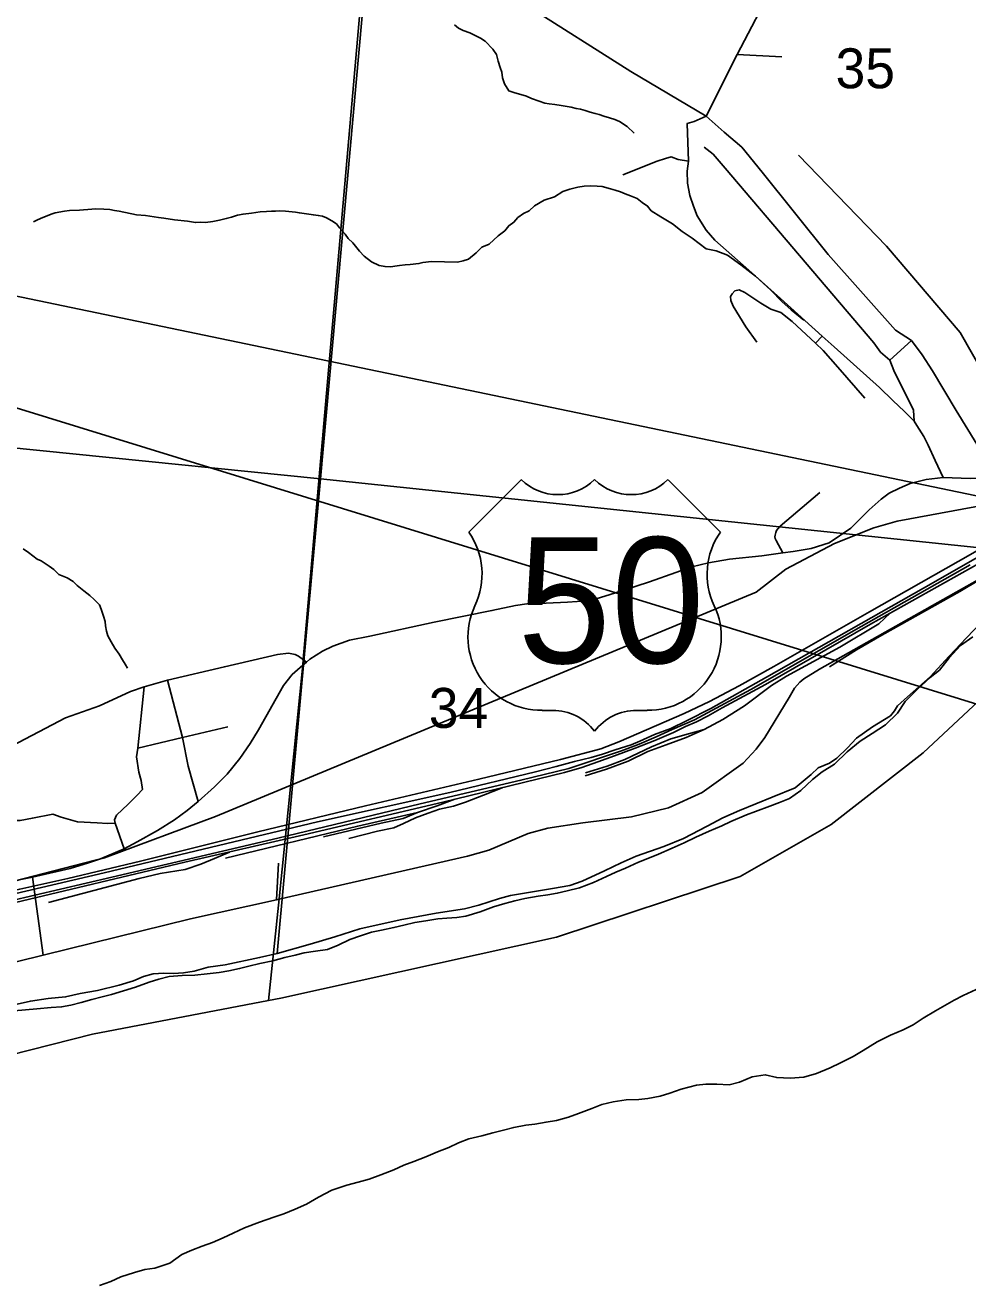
# Model space of a CAD drawing. Extents: x 0 to 34, y -2 to 22.
# Drawn here: x 6.75 to 7.738, y 14.734 to 16.052 of the extents above; entities that cross this region are included whole.
import ezdxf

# ---------------------------------------------------------------- set-up
doc = ezdxf.new("R2010")
doc.units = 0
for name, color, linetype in [('GM_X_City_Street', 7, 'Continuous'), ('GM_X_County_Road', 7, 'Continuous'), ('GM_X_Major_River', 7, 'Continuous'), ('GM_X_Minor_River', 7, 'Continuous'), ('GM_X_Rail_Line', 7, 'Continuous'), ('GM_X_Section', 7, 'Continuous'), ('GM_X_Section_Text', 7, 'Continuous'), ('GM_X_US_Location', 7, 'Continuous'), ('GM_X_US_Route', 7, 'Continuous'), ('GM_X_US_Shield', 7, 'Continuous'), ('SH_Cut_Line', 7, 'Continuous'), ('SH_Data', 7, 'Continuous')]:
    doc.layers.add(name, color=color, linetype=linetype)

msp = doc.modelspace()

# ---------------------------------------------------------------- linework, layer by layer
at = {"layer": 'GM_X_City_Street'}
for p, q in [((7.4964, 16.0209), (7.5431, 16.0184)), ((7.5783, 15.7185), (7.5854, 15.7256)), ((7.6564, 15.7004), (7.6791, 15.7211)), ((7.0137, 15.135), (7.0157, 15.1732)), ((6.7691, 15.077), (6.758, 15.1588))]:
    msp.add_line(p, q, dxfattribs=at)
for points in [[(7.7121, 15.5775), (7.7036, 15.5952), (7.6965, 15.6115), (7.6919, 15.6206), (7.6845, 15.6322), (7.6819, 15.6365), (7.6718, 15.6467), (7.6595, 15.6584), (7.6454, 15.6717), (7.598, 15.7144), (7.5854, 15.7256), (7.5416, 15.765), (7.5084, 15.795), (7.4849, 15.8157), (7.4729, 15.8264), (7.4639, 15.8367), (7.4545, 15.8517), (7.4506, 15.8619), (7.4465, 15.8732), (7.4442, 15.886), (7.444, 15.8987), (7.4453, 15.909), (7.444, 15.9487), (7.4511, 15.9506), (7.4637, 15.9561)], [(7.4453, 15.909), (7.4346, 15.911), (7.4271, 15.9136), (7.4211, 15.912), (7.4123, 15.909), (7.3764, 15.8947)], [(7.6819, 15.6365), (7.6809, 15.648), (7.6603, 15.6898), (7.6564, 15.7004), (7.6466, 15.709), (7.6396, 15.7188), (7.4836, 15.9018), (7.4711, 15.9164), (7.4617, 15.9238)], [(7.82, 15.5775), (7.7958, 15.6223), (7.7543, 15.6867), (7.7301, 15.7295), (7.6526, 15.82), (7.5606, 15.9153)], [(7.6299, 15.6608), (7.6018, 15.6932), (7.5865, 15.7105), (7.5783, 15.7185), (7.554, 15.7412), (7.542, 15.7504), (7.5314, 15.7539), (7.5211, 15.7603), (7.5116, 15.7665), (7.5043, 15.7716), (7.4984, 15.7742), (7.494, 15.7731), (7.491, 15.77), (7.4894, 15.7672), (7.4897, 15.7631), (7.492, 15.7572)], [(7.5168, 15.7193), (7.5053, 15.7353), (7.492, 15.7572)], [(7.5442, 15.4986), (7.537, 15.5114), (7.5361, 15.5136), (7.5359, 15.5153), (7.5361, 15.5172), (7.5367, 15.52), (7.5376, 15.5221), (7.5389, 15.5239), (7.5415, 15.5267), (7.5828, 15.5617)], [(6.6909, 15.0578), (6.7691, 15.077), (6.9235, 15.1148), (7.0137, 15.135), (7.0164, 15.1356), (7.2137, 15.1806), (7.2359, 15.1871), (7.2771, 15.2043), (7.2978, 15.2101), (7.3344, 15.2157), (7.3854, 15.2219), (7.4244, 15.2312), (7.4595, 15.2475), (7.5026, 15.2783), (7.5163, 15.2928), (7.5251, 15.3049), (7.5507, 15.3471), (7.5564, 15.3566), (7.5618, 15.363), (7.5662, 15.3665), (7.5825, 15.3766), (7.8057, 15.5024)], [(6.7293, 15.2925), (6.7926, 15.3256), (6.8279, 15.3381), (6.8606, 15.3531), (6.8747, 15.3582), (6.8994, 15.365), (6.959, 15.3792), (7.0147, 15.392), (7.0262, 15.3933), (7.0332, 15.3919), (7.0367, 15.3903), (7.0418, 15.3864), (7.0448, 15.3839)], [(6.9315, 15.2379), (6.9211, 15.2749), (6.9152, 15.3051), (6.8994, 15.365)], [(6.8539, 15.1885), (6.8444, 15.2153), (6.8438, 15.2188), (6.846, 15.2235), (6.858, 15.2352), (6.8676, 15.2445), (6.8732, 15.2507), (6.8716, 15.26), (6.8694, 15.2686), (6.867, 15.2846), (6.8681, 15.294), (6.8747, 15.3582)], [(6.8681, 15.294), (6.9152, 15.3051), (6.9627, 15.3161)], [(6.6575, 15.1353), (6.6562, 15.1406), (6.6549, 15.1485), (6.6549, 15.1562), (6.6558, 15.1616), (6.661, 15.1682), (6.6808, 15.1838), (6.6889, 15.1904), (6.6944, 15.1967), (6.6977, 15.2048), (6.7006, 15.2098), (6.7123, 15.2165), (6.7244, 15.2182), (6.7448, 15.218), (6.7577, 15.2205), (6.7792, 15.2245), (6.7878, 15.2216), (6.8049, 15.2168), (6.8257, 15.2155), (6.8365, 15.2148), (6.8444, 15.2153)]]:
    msp.add_lwpolyline(points, dxfattribs=at)
at = {"layer": 'GM_X_County_Road'}
for points in [[(7.4637, 15.9561), (7.4964, 16.0209), (7.5352, 16.0954), (7.5404, 16.1047), (7.558, 16.1266), (7.6348, 16.2084), (7.6443, 16.2237), (7.6522, 16.2368), (7.6565, 16.247), (7.6579, 16.2514), (7.6603, 16.2699), (7.6794, 16.4469), (7.6823, 16.4535), (7.6835, 16.4563), (7.6891, 16.469), (7.7056, 16.5046), (7.7084, 16.5106), (7.7098, 16.5193), (7.7437, 16.7928), (7.7563, 16.8973), (7.7576, 16.9073)], [(7.112, 16.1885), (7.1743, 16.1656), (7.1952, 16.1517), (7.2074, 16.1396), (7.2198, 16.1237), (7.2337, 16.1048), (7.2425, 16.0951), (7.2522, 16.0876), (7.2734, 16.0738), (7.3847, 16.003), (7.4637, 15.9561)], [(7.4637, 15.9561), (7.4828, 15.9396), (7.501, 15.9238), (7.5226, 15.8975), (7.5916, 15.8113), (7.6622, 15.7321), (7.6791, 15.7211), (7.69, 15.7062), (7.7008, 15.6892), (7.7259, 15.6477), (7.769, 15.5773)]]:
    msp.add_lwpolyline(points, dxfattribs=at)
at = {"layer": 'GM_X_Major_River'}
for points in [[(7.7432, 15.4105), (7.7304, 15.4014), (7.7183, 15.3884), (7.7082, 15.3757), (7.6985, 15.368), (7.6853, 15.3558), (7.6724, 15.3429), (7.6642, 15.3305), (7.6517, 15.3183), (7.6378, 15.3092), (7.6251, 15.3012), (7.6116, 15.2901), (7.5983, 15.2772), (7.5852, 15.2692), (7.5752, 15.2611), (7.5631, 15.2496), (7.5512, 15.2412), (7.5408, 15.2369), (7.5305, 15.233), (7.5155, 15.2276), (7.506, 15.2241), (7.4898, 15.2169), (7.4803, 15.2126), (7.4668, 15.2069), (7.453, 15.2004), (7.4407, 15.1946), (7.4281, 15.1889), (7.4139, 15.1828), (7.4043, 15.1788), (7.3928, 15.1742), (7.3794, 15.1681), (7.369, 15.1638), (7.3594, 15.1595), (7.3456, 15.153), (7.331, 15.1476), (7.3181, 15.1442), (7.3078, 15.1418), (7.2978, 15.1401), (7.2879, 15.1389), (7.2738, 15.1362), (7.2632, 15.1338), (7.2528, 15.131), (7.241, 15.1275), (7.2268, 15.1222), (7.2119, 15.1176), (7.2024, 15.1163), (7.1921, 15.1155), (7.1826, 15.1149), (7.1701, 15.113), (7.1586, 15.111), (7.1468, 15.1082), (7.1365, 15.1058), (7.1235, 15.1031), (7.1132, 15.1011), (7.1014, 15.0972), (7.0903, 15.0933), (7.078, 15.0872), (7.0669, 15.0829), (7.0543, 15.081), (7.0425, 15.0794), (7.033, 15.0769), (7.0223, 15.0746), (7.0097, 15.0711), (6.9959, 15.068), (6.9845, 15.0653), (6.9749, 15.0628), (6.9635, 15.0605), (6.9536, 15.0588), (6.941, 15.0572), (6.9281, 15.0561), (6.9148, 15.0556), (6.9011, 15.0545), (6.8904, 15.0517), (6.8801, 15.0485), (6.8659, 15.0432), (6.8407, 15.0355)], [(6.8407, 15.0355), (6.8308, 15.0331), (6.8201, 15.0303), (6.809, 15.0272), (6.7979, 15.0244), (6.7884, 15.0227), (6.7774, 15.0219), (6.7625, 15.0207), (6.7504, 15.0195), (6.7386, 15.0187)], [(6.8282, 14.7307), (6.84, 14.735), (6.8504, 14.7397), (6.8649, 14.7442), (6.8756, 14.7474), (6.8859, 14.749), (6.9016, 14.7539), (6.9144, 14.7631), (6.9247, 14.7678), (6.9358, 14.772), (6.9465, 14.7756), (6.9577, 14.7806), (6.968, 14.7856), (6.9799, 14.791), (6.9956, 14.7971), (7.0109, 14.8024), (7.0213, 14.8059), (7.0332, 14.8106), (7.0451, 14.816), (7.0574, 14.8232), (7.0716, 14.8305), (7.0873, 14.8358), (7.0991, 14.8389), (7.1106, 14.842), (7.1228, 14.8466), (7.1366, 14.852), (7.147, 14.8567), (7.1573, 14.8606), (7.17, 14.8656), (7.1822, 14.8706), (7.1941, 14.8752), (7.2041, 14.8803), (7.2152, 14.8845), (7.2286, 14.8876), (7.2404, 14.8907), (7.2515, 14.8935), (7.2622, 14.8963), (7.2748, 14.8986), (7.2843, 14.8999), (7.2961, 14.9019), (7.3071, 14.9035), (7.3194, 14.907), (7.3301, 14.9109), (7.3439, 14.9162), (7.3546, 14.9205), (7.3664, 14.9232), (7.3798, 14.9252), (7.3931, 14.9256), (7.4026, 14.9265), (7.4155, 14.9292), (7.4258, 14.9324), (7.4377, 14.9366), (7.4538, 14.9408), (7.4636, 14.9417), (7.475, 14.9418), (7.4879, 14.9411), (7.4986, 14.9438), (7.512, 14.9492), (7.5257, 14.9515), (7.5378, 14.9485), (7.5518, 14.9478), (7.5663, 14.949), (7.5793, 14.9528), (7.5938, 14.9589), (7.6046, 14.9639), (7.618, 14.9708), (7.6284, 14.977), (7.6431, 14.9861), (7.6569, 14.993), (7.6703, 14.9987), (7.6807, 15.0038), (7.6911, 15.0107), (7.7042, 15.0184), (7.7138, 15.0242), (7.7235, 15.0296), (7.7331, 15.0347), (7.7469, 15.0408)]]:
    msp.add_lwpolyline(points, dxfattribs=at)
at = {"layer": 'GM_X_Minor_River'}
for points in [[(7.3885, 15.9383), (7.3811, 15.9454), (7.3729, 15.9505), (7.368, 15.9526), (7.3624, 15.9546), (7.3567, 15.9563), (7.3518, 15.958), (7.3473, 15.9589), (7.3424, 15.9605), (7.3371, 15.9622), (7.3322, 15.9635), (7.3276, 15.9644), (7.3223, 15.9657), (7.3117, 15.9675), (7.3053, 15.9684), (7.2992, 15.9693), (7.2947, 15.9699), (7.2887, 15.9719), (7.2808, 15.9748), (7.2755, 15.9772), (7.2623, 15.981), (7.257, 15.9827), (7.2523, 15.9901), (7.2502, 15.9966), (7.2496, 16.0023), (7.2478, 16.0073), (7.2457, 16.0139), (7.244, 16.0208), (7.2403, 16.0266), (7.2322, 16.0348), (7.2273, 16.038), (7.2224, 16.0404), (7.2161, 16.0436), (7.2093, 16.0461), (7.2044, 16.0485), (7.1999, 16.0521)], [(7.4061, 15.8571), (7.4024, 15.8621), (7.3968, 15.8657), (7.3916, 15.87), (7.3845, 15.8729), (7.3788, 15.875), (7.3739, 15.877), (7.3683, 15.8787), (7.3634, 15.88), (7.3547, 15.8825), (7.3494, 15.883), (7.3425, 15.8832), (7.3361, 15.883), (7.3292, 15.8817), (7.3208, 15.8796), (7.3135, 15.8772), (7.305, 15.8717), (7.2942, 15.8682), (7.2838, 15.8624), (7.2783, 15.8572), (7.2722, 15.8543), (7.2663, 15.8499), (7.2624, 15.8451), (7.257, 15.8414), (7.2527, 15.8362), (7.2457, 15.8307), (7.2363, 15.8222), (7.2286, 15.819), (7.2228, 15.813), (7.2146, 15.8064), (7.2092, 15.8047), (7.2031, 15.8033), (7.1761, 15.8041), (7.167, 15.8028), (7.1627, 15.8018), (7.1536, 15.8009), (7.1483, 15.8003), (7.1425, 15.7997), (7.1376, 15.799), (7.1334, 15.7984), (7.1273, 15.7986), (7.1212, 15.7999), (7.113, 15.8035), (7.1055, 15.8095), (7.1004, 15.8149), (7.0934, 15.8235), (7.0885, 15.8282), (7.0856, 15.8325), (7.0797, 15.8391), (7.0764, 15.8434), (7.0715, 15.8466), (7.0659, 15.8498), (7.0618, 15.8514), (7.0573, 15.8523), (7.0523, 15.8528), (7.0474, 15.8537), (7.0425, 15.8542), (7.0375, 15.8548), (7.0334, 15.8556), (7.0228, 15.8567), (7.0167, 15.8569), (7.0125, 15.8566), (7.0083, 15.8567), (7.003, 15.8565), (6.9965, 15.8559), (6.9873, 15.8546), (6.9786, 15.8537), (6.9725, 15.8524), (6.9663, 15.8503), (6.9609, 15.8489), (6.9537, 15.8472), (6.9468, 15.8459), (6.9392, 15.8449), (6.9338, 15.8451), (6.9285, 15.8448), (6.9202, 15.8462), (6.9065, 15.8477), (6.8955, 15.8492), (6.8899, 15.8501), (6.8762, 15.852), (6.8667, 15.853), (6.8486, 15.8566), (6.8437, 15.8575), (6.8388, 15.8584), (6.8327, 15.8589), (6.8243, 15.8592), (6.8201, 15.8589), (6.8072, 15.8577), (6.7965, 15.8573), (6.7915, 15.8567), (6.7816, 15.855), (6.7774, 15.8536), (6.7732, 15.8518), (6.7686, 15.8501), (6.7632, 15.8475), (6.7589, 15.8454)], [(7.4061, 15.8571), (7.4163, 15.8508), (7.4286, 15.8433), (7.4387, 15.8355), (7.4492, 15.8285), (7.4637, 15.8171), (7.4743, 15.815), (7.4863, 15.8106), (7.5001, 15.8004), (7.5154, 15.7887), (7.5314, 15.7739), (7.5432, 15.7619), (7.5529, 15.7533), (7.5663, 15.7424)], [(6.7481, 15.5029), (6.7537, 15.499), (6.7627, 15.4919), (6.7668, 15.4902), (6.7754, 15.4847), (6.7802, 15.4811), (6.7854, 15.476), (6.7941, 15.4723), (6.8004, 15.4684), (6.8045, 15.4644), (6.8116, 15.4589), (6.8179, 15.4538), (6.8223, 15.4495), (6.8279, 15.444), (6.8297, 15.4397), (6.8321, 15.4321), (6.8339, 15.4267), (6.8342, 15.4221), (6.8355, 15.4164), (6.8369, 15.4117), (6.8402, 15.4052), (6.8442, 15.3986), (6.8486, 15.3924), (6.8522, 15.3866), (6.8551, 15.3819), (6.8573, 15.3777)]]:
    msp.add_lwpolyline(points, dxfattribs=at)
at = {"layer": 'GM_X_Rail_Line'}
for points in [[(7.3254, 18.3889), (7.2924, 18.0527), (7.2805, 17.9249), (7.2705, 17.818), (7.2479, 17.5755), (7.2301, 17.3765), (7.2142, 17.2276), (7.2013, 17.0768), (7.1819, 16.9294), (7.1729, 16.8603), (7.1419, 16.5212), (7.1299, 16.384), (7.1117, 16.189), (7.0415, 15.3869), (7.041, 15.3813), (7.0162, 15.1361), (7.0052, 15.0295), (7.018, 15.0319), (7.3068, 15.0956), (7.4995, 15.1593), (7.5948, 15.214), (7.6912, 15.289), (7.9856, 15.5639)], [(3.2132, 16.1958), (3.4289, 16.0129), (3.5157, 15.9354), (3.8272, 15.5543), (4.0672, 15.2682), (4.251, 15.1231), (4.3199, 15.0739), (4.5092, 14.9662), (4.7242, 14.8927), (4.942, 14.8608), (5.225, 14.8332), (5.6876, 14.8174), (5.8521, 14.8361), (5.9916, 14.8618), (6.1483, 14.9087), (6.6423, 15.1295), (6.8334, 15.1788), (6.9496, 15.2223), (7.5162, 15.4575), (7.5472, 15.4815), (7.5981, 15.5082), (7.6394, 15.5247), (7.6638, 15.5316), (7.8133, 15.5592)], [(6.0485, 14.702), (6.1464, 14.7771), (6.2416, 14.8366), (6.3391, 14.8719), (6.8207, 14.994), (7.0052, 15.0295), (7.0162, 15.1361), (7.041, 15.3813), (7.0415, 15.3869), (7.1117, 16.189)], [(6.6146, 15.1059), (6.6312, 15.1147), (6.6662, 15.1263), (6.7028, 15.1364), (6.7444, 15.1462), (6.795, 15.1573), (6.871, 15.1755), (6.994, 15.2061), (7.1067, 15.2333), (7.2257, 15.2613), (7.311, 15.282), (7.3534, 15.293), (7.3722, 15.3005), (7.4409, 15.3303), (7.4674, 15.3427), (7.4983, 15.3593), (7.5346, 15.3794), (7.6351, 15.4369), (7.7278, 15.4896), (7.8167, 15.5401), (7.8706, 15.57), (7.8897, 15.5778), (7.9146, 15.5882)], [(6.833, 15.1632), (7.0564, 15.2165), (7.1953, 15.2475), (7.2848, 15.2692), (7.3066, 15.2746), (7.3257, 15.28), (7.3433, 15.2839), (7.3552, 15.2874), (7.3684, 15.2921), (7.3853, 15.2972), (7.3942, 15.3012), (7.4097, 15.3082), (7.4267, 15.3146), (7.4438, 15.3227), (7.4688, 15.3355), (7.5269, 15.3683), (7.702, 15.4676), (7.8432, 15.5481), (7.9089, 15.585), (7.9146, 15.5882)], [(7.5931, 15.3792), (7.6214, 15.397), (7.6477, 15.4122), (7.7296, 15.4582), (7.7514, 15.4709), (7.7645, 15.4821), (7.7706, 15.4909), (7.777, 15.4998), (7.7912, 15.511)], [(6.7327, 15.1303), (6.9174, 15.1742), (7.0421, 15.2029), (7.1879, 15.2374), (7.3155, 15.2682), (7.3336, 15.2737), (7.3504, 15.2795), (7.3677, 15.2858), (7.3894, 15.2938), (7.41, 15.302), (7.4294, 15.3103), (7.4422, 15.3165), (7.4535, 15.3215), (7.466, 15.3277), (7.4807, 15.3361), (7.5258, 15.3607), (7.636, 15.4237), (7.7757, 15.5021)], [(7.7403, 15.4861), (7.6263, 15.4214), (7.5105, 15.3554), (7.4515, 15.3235), (7.428, 15.3133), (7.4114, 15.3056), (7.3935, 15.2981), (7.3751, 15.2911), (7.3199, 15.2725), (7.2697, 15.2603), (7.1642, 15.2356), (7.0148, 15.1995), (6.8409, 15.1586), (6.7334, 15.1336)], [(7.4617, 15.3133), (7.4814, 15.324), (7.5038, 15.3381), (7.5322, 15.3595), (7.548, 15.3692), (7.6037, 15.3996), (7.6449, 15.424), (7.6567, 15.4353)], [(7.3369, 15.2649), (7.3592, 15.2717), (7.3821, 15.2803), (7.4027, 15.2902), (7.422, 15.2972), (7.443, 15.3049), (7.4617, 15.3133)], [(7.3373, 15.268), (7.36, 15.2749), (7.3784, 15.2819), (7.4065, 15.2953), (7.4266, 15.3036), (7.4453, 15.3088), (7.4617, 15.3133)], [(7.2501, 15.2524), (7.2306, 15.2445), (7.2116, 15.2373), (7.1989, 15.2331), (7.1844, 15.2298), (7.1725, 15.2256), (7.1592, 15.2209), (7.1466, 15.2148), (7.1364, 15.2104), (7.1195, 15.2069), (7.0892, 15.1991)], [(7.2003, 15.2404), (7.1818, 15.2335), (7.1612, 15.2263)], [(7.1612, 15.2263), (7.0986, 15.2121), (6.96, 15.1787)], [(7.1612, 15.2263), (7.1461, 15.2202), (7.1233, 15.2153), (7.0628, 15.2009)], [(6.7746, 15.1322), (6.8695, 15.1571), (6.8917, 15.1624), (6.918, 15.1668), (6.9343, 15.1723), (6.9486, 15.1782), (6.9643, 15.185)], [(5.906, 14.8342), (5.9354, 14.8392), (5.9688, 14.8461), (6.0064, 14.8549), (6.0302, 14.8613), (6.0619, 14.8708), (6.0856, 14.8783), (6.1062, 14.8854), (6.1226, 14.8912), (6.1385, 14.8972), (6.1578, 14.9048), (6.1797, 14.914), (6.2093, 14.927), (6.2632, 14.9508), (6.3927, 15.0082), (6.5799, 15.0916), (6.605, 15.1021), (6.6251, 15.11), (6.642, 15.1158), (6.6615, 15.1219), (6.6847, 15.1285), (6.833, 15.1632)]]:
    msp.add_lwpolyline(points, dxfattribs=at)
at = {"layer": 'GM_X_Section'}
for points in [[(7.1499, 16.5781), (7.0595, 15.5763), (6.0281, 15.6802), (6.1288, 16.703)], [(8.1243, 16.4653), (8.036, 15.6699), (8.0185, 15.6495), (8.0091, 15.6379), (8.0044, 15.6324), (7.9936, 15.622), (7.9816, 15.6105), (7.958, 15.591), (7.9342, 15.576), (7.9154, 15.5647), (7.9046, 15.5577), (7.8981, 15.5526), (7.864, 15.5196), (7.8404, 15.4978), (7.8376, 15.4949), (7.0595, 15.5763), (7.1499, 16.5781)]]:
    msp.add_lwpolyline(points, close=True, dxfattribs=at)
for points in [[(6.0281, 15.6802), (7.0595, 15.5763), (7.0141, 15.0788), (6.9958, 15.0743), (6.9596, 15.0668), (6.9418, 15.0642), (6.9273, 15.06), (6.9162, 15.0584), (6.9056, 15.0578), (6.8954, 15.0581), (6.8844, 15.0572), (6.8741, 15.0544), (6.8638, 15.0501), (6.8485, 15.0455), (6.826, 15.04), (6.8078, 15.0366), (6.7925, 15.0331), (6.7743, 15.0313), (6.7557, 15.0287), (6.7386, 15.0249)], [(7.7535, 15.4271), (7.7361, 15.4093), (7.7186, 15.3904), (7.6984, 15.3685), (7.6748, 15.3475), (7.6644, 15.3382), (7.6612, 15.333), (7.6569, 15.3278), (7.6381, 15.3161), (7.6212, 15.3044), (7.6118, 15.2943), (7.6006, 15.2832), (7.5929, 15.2781), (7.581, 15.2731), (7.5737, 15.2661), (7.5571, 15.2524), (7.533, 15.2424), (7.4986, 15.2284), (7.4814, 15.2208), (7.4649, 15.2121), (7.4399, 15.199), (7.4193, 15.1908), (7.3903, 15.1808), (7.3746, 15.1736), (7.3574, 15.1653), (7.334, 15.1545), (7.321, 15.1499), (7.3028, 15.1469), (7.2586, 15.1395), (7.2472, 15.1364), (7.2255, 15.1293), (7.2106, 15.1255), (7.1809, 15.1209), (7.1433, 15.1138), (7.101, 15.1045), (7.0747, 15.096), (7.0487, 15.0883), (7.0141, 15.0788), (7.0595, 15.5763), (7.8376, 15.4949)]]:
    msp.add_lwpolyline(points, dxfattribs=at)
at = {"layer": 'GM_X_US_Route'}
for points in [[(7.5442, 15.4986), (7.5549, 15.4999), (7.5739, 15.5031), (7.5927, 15.5089), (7.6154, 15.5243), (7.6345, 15.5437), (7.6471, 15.5548), (7.6554, 15.5611), (7.6663, 15.5665), (7.6776, 15.5711), (7.6945, 15.5753), (7.7121, 15.5775), (7.7405, 15.5764), (7.769, 15.5773), (7.8026, 15.577), (7.82, 15.5775), (7.8365, 15.5784), (7.8458, 15.5805)], [(7.0448, 15.3839), (7.0484, 15.3871), (7.0618, 15.3956), (7.0725, 15.4009), (7.0899, 15.4071), (7.1113, 15.4114), (7.1787, 15.4258), (7.2393, 15.438), (7.264, 15.4435), (7.2758, 15.445), (7.296, 15.4459), (7.3186, 15.4469), (7.3387, 15.4483), (7.3494, 15.4506), (7.3623, 15.4545), (7.3776, 15.4594), (7.4043, 15.4681), (7.4321, 15.4779), (7.4489, 15.4838), (7.4661, 15.4881), (7.4884, 15.4918), (7.5222, 15.4955), (7.5442, 15.4986)], [(6.8165, 15.1738), (6.829, 15.1779), (6.8539, 15.1885), (6.8675, 15.1956), (6.889, 15.2075), (6.9068, 15.2189), (6.9198, 15.2286), (6.9315, 15.2379), (6.9486, 15.2532), (6.9618, 15.2667), (6.9752, 15.2831), (6.986, 15.2988), (6.9946, 15.313), (7.0208, 15.3594), (7.03, 15.371), (7.0412, 15.3807), (7.0448, 15.3839)], [(6.7178, 15.1504), (6.7319, 15.1533), (6.758, 15.1588), (6.7972, 15.1676), (6.8165, 15.1738)]]:
    msp.add_lwpolyline(points, dxfattribs=at)
at = {"layer": 'GM_X_US_Shield'}
for p, q in [((7.27, 15.5752), (7.215, 15.5203)), ((7.4787, 15.5203), (7.4238, 15.5752)), ((7.2919, 15.3335), (7.3029, 15.3335)), ((7.3908, 15.3335), (7.4018, 15.3335))]:
    msp.add_line(p, q, dxfattribs=at)
for centre, radius, start, end in [((7.3084, 15.6145), 0.0549, 225.573, 314.427), ((7.3853, 15.6145), 0.0549, 225.573, 314.427), ((7.152, 15.4762), 0.0769, 334.5471, 35.0009), ((7.5417, 15.4762), 0.0769, 144.9991, 205.4529), ((7.2911, 15.4104), 0.0769, 154.8319, 270.6383), ((7.4027, 15.4104), 0.0769, 269.3617, 25.1681), ((7.3029, 15.2786), 0.0549, 36.8699, 90), ((7.3908, 15.2786), 0.0549, 90, 143.1301)]:
    msp.add_arc(centre, radius, start, end, dxfattribs=at)
at = {"layer": 'SH_Cut_Line'}
msp.add_lwpolyline([(6.0485, 14.702), (6.1464, 14.7771), (6.2416, 14.8366), (6.3391, 14.8719), (6.8207, 14.994), (7.0052, 15.0295), (7.018, 15.0319), (7.3068, 15.0956), (7.4995, 15.1593), (7.5948, 15.214), (7.6912, 15.289), (7.9856, 15.5639), (8.2003, 15.8586), (8.2596, 15.9572), (8.5337, 16.2495), (8.6286, 16.3042), (8.7283, 16.3459), (8.827, 16.358), (8.9, 16.3574), (8.9, 20.9), (2.1, 20.9)], dxfattribs=at)
at = {"layer": 'SH_Data'}
msp.add_lwpolyline([(5.5742, 16.0105), (9.9214, 14.669), (9.9247, 15.1051)], close=True, dxfattribs=at)

# ---------------------------------------------------------------- texts
at = {"layer": 'GM_X_Section_Text'}
for s, p in [('35', (7.5994, 15.9855)), ('34', (7.1731, 15.3151))]:
    msp.add_text(s, height=0.04186, rotation=0, dxfattribs=at).set_placement(p)
at = {"layer": 'GM_X_US_Location'}
for s in ['0', '/']:
    msp.add_text(s, height=0.000189, dxfattribs=at).set_placement((7.3468, 15.4478))
msp.add_text('50', height=0.000189, rotation=0, dxfattribs=at).set_placement((7.3077, 15.4086))
at = {"layer": 'GM_X_US_Shield'}
msp.add_text('50', height=0.13184, dxfattribs=at).set_placement((7.266, 15.383))

doc.saveas('drawing.dxf')
